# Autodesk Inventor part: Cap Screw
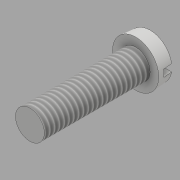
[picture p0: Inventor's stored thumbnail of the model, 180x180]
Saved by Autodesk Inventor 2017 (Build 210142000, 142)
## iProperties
Created: 2016-05
Part Number: Cap Screw
Material: Generic
Document SubType Name: Modeling
Designer: CADCIM
Density: 1 g/cm^3
Appearance: Default
Author: CADCIM
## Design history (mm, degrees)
sketch "Sketch2"
  geometry: C1 r 4.8 at (0, 0); 1 further point
  constraints: 1 centre point, 1 coincident
  dimensions: "d0" = 9.6 diameter of C1
extrude "Extrusion1" new body sketch "Sketch2" distance "d1" = 3; taper "d2" = -5 deg
sketch "Sketch3"
  geometry: C1 r 3 at (0, 0); 1 further point
  constraints: 1 centre point, 1 coincident
  dimensions: "d3" = 6 diameter of C1
extrude "Extrusion2" join sketch "Sketch3" distance "d4" = 22; taper "d5" = 0 deg
sketch "Sketch4"
  geometry: L1 (-13.358, -0.75)-(13.048, -0.75); L2 (13.048, -0.75)-(13.048, 0.75); L3 (13.048, 0.75)-(-13.358, 0.75); L4 (-13.358, 0.75)-(-13.358, -0.75); L5 (0, 0)-(-15.613, 0)
  constraints: 10 end point, 3 parallel, 1 horizontal, 1 perpendicular, 1 other
  dimensions: "d6" = 1.5 distance of L3.end L1.start
extrude "Extrusion3" cut sketch "Sketch4" distance "d7" = 1.8; taper "d8" = 0 deg
thread "Thread1" dims "d9" = 10, "d10" = 0
body "Solid1"
